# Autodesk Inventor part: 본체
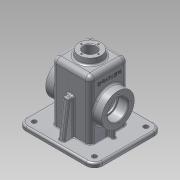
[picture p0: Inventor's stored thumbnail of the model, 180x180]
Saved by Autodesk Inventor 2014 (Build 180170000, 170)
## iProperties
Created: 2016-08
Part Number: 본체
Material: 알루미늄 6061
Document SubType Name: Modeling
Designer: user
Density: 2.71 g/cm^3
Appearance: 알루미늄 - 평지
Mass: 796.088 g
Surface Area: 911.213 cm^2
Volume: 293.76 cm^3
Author: user
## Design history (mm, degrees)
sketch "스케치1"
  geometry: L1 (0, 0)-(130, 0); L2 (130, 0)-(130, 115); L3 (130, 115)-(0, 115); L4 (0, 115)-(0, 0)
  constraints: 8 end point, 2 parallel, 1 horizontal, 1 perpendicular
  dimensions: "d0" = 130 distance of L3.end L2.end; "d1" = 115 distance of L2.end L1.end
extrude "돌출1" new body sketch "스케치1" distance "d2" = 7; taper "d3" = 0 deg
sketch "스케치2"
  geometry: L1 (32.5, 25)-(97.5, 25); L2 (97.5, 25)-(97.5, 90); L3 (97.5, 90)-(32.5, 90); L4 (32.5, 90)-(32.5, 25); L5 (130, 115)-(0, 115) reference; L6 (0, 115)-(0, 0) reference
  constraints: 8 end point, 2 parallel, 1 horizontal, 1 perpendicular
  dimensions: "d4" = 65 distance of L3.end L2.end; "d5" = 65 distance of L2.end L1.end; "d6" = 25 distance between parallel lines of L5 L3; "d7" = 32.5 distance between parallel lines of L6 L4
extrude "돌출2" join sketch "스케치2" distance "d8" = 100; taper "d9" = 0 deg
fillet "모깎기1" dims "d10" = 14
sketch "스케치3"
  geometry: L1 (32.5, 25)-(97.5, 25) reference; L2 (97.5, 25)-(97.5, 90) reference; L3 (97.5, 90)-(32.5, 90) reference; L4 (32.5, 90)-(32.5, 25) reference; L5 (97.5, 90)-(32.5, 90) reference; L6 (32.5, 90)-(32.5, 25) reference; C1 r 20 at (65, 57.5); 3 further points
  constraints: 2 midpoint, 1 centre point, 1 horizontal alignment, 1 vertical alignment
  dimensions: "d11" = 40 diameter of C1
extrude "돌출3" join sketch "스케치3" distance "d12" = 10; taper "d13" = 0 deg
sketch "스케치4"
  geometry: L1 (0, 0)-(0, 65) reference; L2 (0, 0)-(100, 0) reference; L3 (100, 65)-(100, 0) reference; L4 (0, 65)-(100, 65) reference; L5 (0, 76)-(0, -11) reference; L6 (-7, 76)-(-7, -11) reference; C1 r 27.5 at (45, 32.5); 2 further points
  constraints: 1 centre point, 1 horizontal alignment, 1 midpoint
  dimensions: "d14" = 55 diameter of C1; "d15" = 52 distance from line of L6 C1.centre
extrude "돌출4" join sketch "스케치4" distance "d16" = 15; taper "d17" = 0 deg
sketch "스케치5"
  geometry: L1 (7, -11)-(7, 76) reference; C1 r 27.5 at (-45, 32.5); 2 further points
  constraints: 1 centre point, 1 horizontal alignment, 1 midpoint
  dimensions: "d18" = 55 diameter of C1; "d19" = 52 distance from line of L1 C1.centre
extrude "돌출5" join sketch "스케치5" distance "d20" = 15; taper "d21" = 0 deg
sketch "스케치7"
  geometry: L1 (-37.5, 30)-(-92.5, 30); L2 (-92.5, 30)-(-92.5, 85); L3 (-92.5, 85)-(-37.5, 85); L4 (-37.5, 85)-(-37.5, 30); L5 (-14, 0)-(-116, 0) reference; L6 (0, 101)-(0, 14) reference; 5 further points
  constraints: 8 end point, 4 midpoint, 2 parallel, 1 horizontal, 1 horizontal alignment, 1 perpendicular, 1 vertical alignment
  dimensions: "d22" = 55 distance of L2.end L3.end; "d23" = 55 distance of L1.end L2.end
extrude "돌출6" cut sketch "스케치7" distance "d24" = 102; taper "d25" = 0 deg
sketch "스케치8"
  geometry: L1 (37.5, 85)-(37.5, 30) reference; L2 (37.5, 30)-(92.5, 30) reference; L3 (92.5, 30)-(92.5, 85) reference; L4 (92.5, 85)-(37.5, 85) reference; L5 (130, 14)-(130, 101) reference; L6 (14, 0)-(116, 0) reference; L7 (0, 101)-(0, 14) reference; L8 (116, 115)-(14, 115) reference; L9 (22.5, 60.5)-(37.5, 60.5); L10 (37.5, 60.5)-(37.5, 54.5); L11 (37.5, 54.5)-(22.5, 54.5); L12 (22.5, 54.5)-(22.5, 60.5); L13 (92.5, 60.5)-(107.5, 60.5); L14 (107.5, 60.5)-(107.5, 54.5); L15 (107.5, 54.5)-(92.5, 54.5); L16 (92.5, 54.5)-(92.5, 60.5); A1 r 14 centre (116, 101) between (130, 101) and (116, 115) reference; A2 r 14 centre (116, 14) between (116, 0) and (130, 14) reference; A3 r 14 centre (14, 14) between (0, 14) and (14, 0) reference; A4 r 14 centre (14, 101) between (14, 115) and (0, 101) reference; 5 further points
  constraints: 16 end point, 4 midpoint, 4 parallel, 2 horizontal, 2 horizontal alignment, 2 perpendicular, 2 point on line
  dimensions: "d26" = 15 distance of L10.end L11.end; "d27" = 15 distance of L14.end L15.end; "d28" = 6 distance of L11.end L9.start; "d29" = 6 distance of L13.end L14.end
extrude "돌출7" join sketch "스케치8" stored distance "d30" = 105; taper "d31" = 0 deg
sketch "스케치9"
  geometry: L1 (37.5, 85)-(37.5, 30) reference; L2 (37.5, 30)-(92.5, 30) reference; L3 (92.5, 30)-(92.5, 85) reference; L4 (92.5, 85)-(37.5, 85) reference; L5 (130, 14)-(130, 101) reference; L6 (14, 0)-(116, 0) reference; L7 (0, 101)-(0, 14) reference; L8 (116, 115)-(14, 115) reference; L9 (70, 8)-(60, 8); L10 (60, 8)-(60, 30); L11 (60, 30)-(70, 30); L12 (70, 30)-(70, 8); L13 (70, 85)-(60, 85); L14 (60, 85)-(60, 107); L15 (60, 107)-(70, 107); L16 (70, 107)-(70, 85); A1 r 14 centre (116, 101) between (130, 101) and (116, 115) reference; A2 r 14 centre (116, 14) between (116, 0) and (130, 14) reference; A3 r 14 centre (14, 14) between (0, 14) and (14, 0) reference; A4 r 14 centre (14, 101) between (14, 115) and (0, 101) reference; 5 further points
  constraints: 16 end point, 4 midpoint, 4 parallel, 2 horizontal, 2 perpendicular, 2 point on line, 2 vertical alignment
  dimensions: "d32" = 8 distance between parallel lines of L9 L6; "d33" = 8 distance between parallel lines of L8 L15; "d34" = 10 distance of L9.start L9.end; "d35" = 10 distance of L14.end L15.end
extrude "돌출8" join sketch "스케치9" distance "d36" = 60; taper "d37" = 0 deg
feature "면 기울기1" dims angle "d38" = 8 deg
fillet "모깎기2" dims "d39" = 8
fillet "모깎기3" dims "d40" = 8
hole "구멍1" diameter "d43" = 21; stored, may be unused: countersink angle "d47" = 90 deg, drill point angle "d49" = 118 deg; dims "d44" = 6, "d45" = 4, "d46" = 2, "d48" = 8, "d50" = 10, "d51" = 10
hole "구멍2" diameter "d54" = 30; stored, may be unused: countersink angle "d58" = 90 deg, drill point angle "d60" = 118 deg; dims "d52" = 10, "d53" = 10, "d55" = 6, "d56" = 4, "d57" = 2, "d59" = 8
hole "구멍3" diameter "d63" = 35; stored, may be unused: countersink angle "d67" = 90 deg, drill point angle "d69" = 0 deg; dims "d64" = 6, "d65" = 4, "d66" = 2, "d68" = 17, "d79" = 10, "d80" = 10
hole "구멍4" diameter "d72" = 35; stored, may be unused: countersink angle "d76" = 90 deg, drill point angle "d78" = 0 deg; dims "d70" = 10, "d71" = 10, "d73" = 6, "d74" = 4, "d75" = 2, "d77" = 17
fillet "모깎기4" dims "d81" = 0.3
fillet "모깎기5" dims "d82" = 3
fillet "모깎기6" dims "d83" = 3
fillet "모깎기7" dims "d84" = 3
fillet "모깎기8" dims "d85" = 3
feature "면 기울기2" dims angle "d86" = 7 deg
fillet "모깎기9" dims "d87" = 3
fillet "모깎기10" dims "d88" = 3
fillet "모깎기11" dims "d89" = 3
fillet "모깎기12" dims "d90" = 1
sketch "스케치10"
  geometry: L1 (-14, 5)-(-116, 5); L2 (-125, 14)-(-125, 101); L3 (-116, 110)-(-14, 110); L4 (-5, 101)-(-5, 14); L5 (-37.5, 82)-(-37.5, 33) reference; L6 (-40.5, 30)-(-89.5, 30) reference; L7 (-92.5, 33)-(-92.5, 82) reference; L8 (-89.5, 85)-(-40.5, 85) reference; L9 (-130, 14)-(-130, 101) reference; L10 (-14, 0)-(-116, 0) reference; L11 (0, 101)-(0, 14) reference; L12 (-116, 115)-(-14, 115) reference; L13 (-14, 0)-(-116, 0) reference; A1 r 3 centre (-40.5, 33) between (-40.5, 30) and (-37.5, 33) reference; A2 r 3 centre (-89.5, 33) between (-92.5, 33) and (-89.5, 30) reference; A3 r 3 centre (-89.5, 82) between (-89.5, 85) and (-92.5, 82) reference; A4 r 3 centre (-40.5, 82) between (-37.5, 82) and (-40.5, 85) reference; A5 r 14 centre (-116, 101) between (-116, 115) and (-130, 101) reference; A6 r 14 centre (-116, 14) between (-130, 14) and (-116, 0) reference; A7 r 14 centre (-14, 14) between (-14, 0) and (0, 14) reference; A8 r 14 centre (-14, 101) between (0, 101) and (-14, 115) reference; A9 r 9 centre (-14, 14) between (-14, 5) and (-5, 14); A10 r 9 centre (-14, 101) between (-5, 101) and (-14, 110); A11 r 9 centre (-116, 101) between (-116, 110) and (-125, 101); A12 r 9 centre (-116, 14) between (-125, 14) and (-116, 5); 8 further points
  constraints: 8 end point, 8 point on circle, 8 tangent, 6 point on line, 4 centre point, 4 midpoint, 2 equal radius, 2 parallel, 1 horizontal, 1 horizontal alignment, 1 perpendicular, 1 vertical alignment
  dimensions: "d91" = 120 distance of point (-125, 110) point (-5, 110); "d92" = 105 distance of point (-125, 5) point (-125, 110); "d93" = 9 radius of A9; "d94" = 9 radius of A10
extrude "돌출9" join sketch "스케치10" distance "d95" = 3; taper "d96" = 0 deg
fillet "모깎기13" dims "d97" = 3
sketch "스케치11"
  geometry: L1 (-40.5, 30)-(-89.5, 30) reference; L2 (-92.5, 33)-(-92.5, 82) reference; L3 (-89.5, 85)-(-40.5, 85) reference; L4 (-37.5, 82)-(-37.5, 33) reference; L5 (-5, 14)-(-5, 101) reference; L6 (-14, 110)-(-116, 110) reference; L7 (-125, 101)-(-125, 14) reference; L8 (-116, 5)-(-14, 5) reference; C1 r 4 at (-14, 14); C2 r 4 at (-116, 14); C3 r 4 at (-116, 101); C4 r 4 at (-14, 101); A1 r 3 centre (-40.5, 33) between (-40.5, 30) and (-37.5, 33) reference; A2 r 3 centre (-89.5, 33) between (-92.5, 33) and (-89.5, 30) reference; A3 r 3 centre (-89.5, 82) between (-89.5, 85) and (-92.5, 82) reference; A4 r 3 centre (-40.5, 82) between (-37.5, 82) and (-40.5, 85) reference; A5 r 9 centre (-14, 101) between (-5, 101) and (-14, 110) reference; A6 r 9 centre (-116, 101) between (-116, 110) and (-125, 101) reference; A7 r 9 centre (-116, 14) between (-125, 14) and (-116, 5) reference; A8 r 9 centre (-14, 14) between (-14, 5) and (-5, 14) reference; 1 further point
  constraints: 4 centre point, 4 coincident
  dimensions: "d98" = 8 diameter of C1; "d99" = 8 diameter of C2; "d100" = 8 diameter of C3; "d101" = 8 diameter of C4
extrude "돌출10" cut sketch "스케치11" distance "d102" = 10; taper "d103" = 0 deg
chamfer "모따기1" distance "d104" = 1; stored, may be unused: second distance "d105" = 2, angle "d106" = 45 deg
sketch "스케치12"
  geometry: L1 (-55, -43.5)-(-55, 43.5) reference; L2 (47, 24.5)-(47, -24.5) reference; L3 (47, 32.5)-(-44, 32.5) reference; L4 (-44, -32.5)-(47, -32.5) reference; L5 (-52, 43.5)-(-52, -43.5) reference; A1 r 21 centre (0, 0) between (21, 0) and (0, -21); 2 further points
  constraints: 4 point on circle, 1 centre point
  dimensions: "d107" = 42 diameter of A1; "d145" = 55 distance from line of L1 A1.centre; "d146" = 26 distance from line of L2 A1.start; "d147" = 11.5 distance from line of L3 point (0, 21); "d148" = 11.5 distance from line of L4 A1.end; "d149" = 31 distance from line of L5 point (-21, 0); "d150" = 32.5 distance from line of L3 A1.centre
hole "구멍5" sketch "스케치12" at (21, 0), (0, -21), (-21, 0), (0, 21) diameter "d108" = 3.242; stored, may be unused: countersink angle "d112" = 90 deg, drill point angle "d114" = 118 deg; dims "d109" = 8, "d110" = 4, "d111" = 2, "d113" = 10
sketch "스케치13"
  geometry: L1 (55, 43.5)-(55, -43.5) reference; L2 (-47, -24.5)-(-47, 24.5) reference; L3 (-47, -32.5)-(44, -32.5) reference; L4 (-47, 24.5)-(-18.166, 24.5) reference; A1 r 21 centre (0, 0) between (-21, 0) and (0, 21); 2 further points
  constraints: 4 point on circle, 1 centre point
  dimensions: "d115" = 42 diameter of A1; "d151" = 55 distance from line of L1 A1.centre; "d152" = 26 distance from line of L2 A1.start; "d153" = 11.5 distance from line of L3 point (0, -21); "d154" = 3.5 distance from line of L4 A1.end; "d155" = 34 distance from line of point (21, 0) L1; "d156" = 24.5 distance from line of point (21, 0) L4
hole "구멍6" sketch "스케치13" at (-21, 0), (0, 21), (21, 0), (0, -21) diameter "d121" = 3.242; stored, may be unused: countersink angle "d125" = 90 deg, drill point angle "d127" = 118 deg; dims "d122" = 8, "d123" = 4, "d124" = 2, "d126" = 10
sketch "스케치14"
  geometry: L1 (-24.5, -24.5)-(-24.5, 24.5) reference; L2 (-24.5, 24.5)-(24.5, 24.5) reference; L3 (24.5, 24.5)-(24.5, -24.5) reference; L4 (51, -54.5)-(-51, -54.5) reference; L5 (-51, -57.5)-(51, -57.5) reference; L6 (51, 57.5)-(-51, 57.5) reference; A1 r 14.5 centre (0, 0) between (-14.5, 0) and (14.5, 0); 2 further points
  constraints: 4 point on circle, 1 centre point
  dimensions: "d133" = 29 diameter of A1; "d165" = 10 distance from line of L1 A1.start; "d166" = 10 distance from line of L2 point (0, 14.5); "d167" = 10 distance from line of L3 A1.end; "d168" = 40 distance from line of L4 point (0, -14.5); "d169" = 57.5 distance from line of L5 A1.start; "d170" = 57.5 distance from line of L6 A1.end
hole "구멍7" sketch "스케치14" at (-14.5, 0), (14.5, 0), (0, 14.5), (0, -14.5) diameter "d134" = 2.459; stored, may be unused: countersink angle "d138" = 90 deg, drill point angle "d140" = 118 deg; dims "d135" = 7, "d136" = 4, "d137" = 2, "d139" = 9
sketch "스케치15"
  geometry: L1 (0, -8)-(91, -8) reference; L2 (-18, 43.272)-(-18, 5.728) reference; 2 further points
  constraints: 1 other
  dimensions: "d141" = 32.5 distance from line of L1 point (8, 24.5); "d142" = 26 distance from line of L2 point (8, 24.5)
feature "엠보싱1" sketch "스케치15" dims "d143" = 0.5, "d144" = 0
node "솔리드1"
node "투영된 루프1"
node "투영된 루프2"
node "투영된 루프3"
node "투영된 루프4"
node "투영된 루프5"
node "투영된 루프6"
